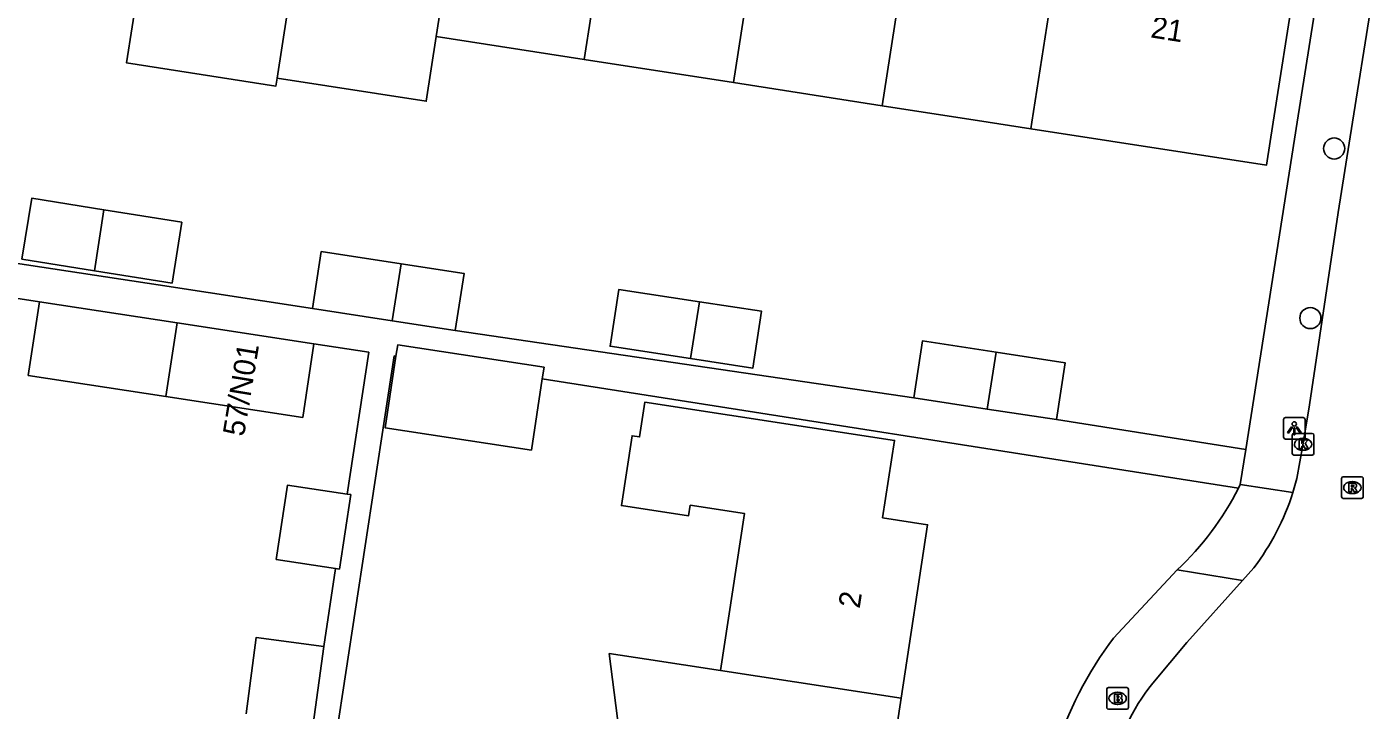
# Model space of a CAD drawing. Extents: x 161486 to 162249, y 379484 to 380829.
# Drawn here: x 162025.3 to 162087.4, y 380472.8 to 380504.4 of the extents above; entities that cross this region are included whole.
import ezdxf

# ---------------------------------------------------------------- set-up
doc = ezdxf.new("R2010")
doc.units = 0
for name, color, linetype in [('IMGEO_Boom', 7, 'Continuous'), ('IMGEO_Brandkraan', 7, 'Continuous'), ('IMGEO_Kolk', 7, 'Continuous'), ('IMGEO_Lichtpunt', 7, 'Continuous'), ('IMGEO_Pand', 7, 'Continuous'), ('IMGEO_Pand_nummerreeks', 7, 'Continuous'), ('IMGEO_Rijbaan_lokaal_open', 7, 'Continuous'), ('IMGEO_Rioolput', 7, 'Continuous'), ('IMGEO_Voetpad_open', 7, 'Continuous')]:
    doc.layers.add(name, color=color, linetype=linetype)

msp = doc.modelspace()

# ---------------------------------------------------------------- linework, layer by layer
at = {"layer": 'IMGEO_Boom'}
for centre in [(162085.83, 380498.777), (162084.729, 380490.922)]:
    msp.add_circle(centre, 0.489, dxfattribs=at)
at = {"layer": 'IMGEO_Brandkraan'}
for p, q in [((162075.306, 380472.888), (162075.306, 380473.74)), ((162075.381, 380473.814), (162076.233, 380473.814)), ((162075.794, 380473.594), (162075.819, 380473.594)), ((162076.307, 380473.74), (162076.307, 380472.888)), ((162076.233, 380472.814), (162075.381, 380472.814)), ((162075.817, 380473.034), (162075.792, 380473.034))]:
    msp.add_line(p, q, dxfattribs=at)
for points in [[(162075.306, 380472.888), (162075.306, 380473.74)], [(162075.381, 380473.814), (162076.233, 380473.814)], [(162075.654, 380473.514), (162075.654, 380473.114), (162075.867, 380473.114)], [(162075.885, 380473.514), (162075.654, 380473.514)], [(162075.833, 380473.433), (162075.779, 380473.433), (162075.779, 380473.357)], [(162075.779, 380473.357), (162075.832, 380473.357)], [(162075.841, 380473.281), (162075.779, 380473.281), (162075.779, 380473.2)], [(162075.779, 380473.2), (162075.841, 380473.2)], [(162076.307, 380473.74), (162076.307, 380472.888)], [(162076.233, 380472.814), (162075.381, 380472.814)]]:
    msp.add_lwpolyline(points, dxfattribs=at)
for centre, radius, start, end in [((162075.383, 380473.738), 0.0765, 91.55205, 178.44795), ((162075.383, 380473.738), 0.0765, 91.55205, 178.44795), ((162075.834, 380473.395), 0.0379, 267.82845, 90.93552), ((162075.842, 380473.24), 0.0404, 269.87594, 90.50774), ((162075.889, 380473.369), 0.145, 59.4692, 91.53667), ((162075.914, 380473.416), 0.0922, 285.51372, 58.15012), ((162075.919, 380473.224), 0.105, 301.31148, 78.98903), ((162076.231, 380473.738), 0.0765, 1.55205, 88.44795), ((162076.231, 380473.738), 0.0765, 1.55205, 88.44795), ((162075.383, 380472.89), 0.0765, 181.55205, 268.44795), ((162075.383, 380472.89), 0.0765, 181.55205, 268.44795), ((162075.873, 380473.365), 0.251, 268.66757, 293.53466), ((162076.231, 380472.89), 0.0765, 271.55205, 358.44795), ((162076.231, 380472.89), 0.0765, 271.55205, 358.44795)]:
    msp.add_arc(centre, radius, start, end, dxfattribs=at)
for centre, major_axis, ratio, start_param, end_param in [((162075.793, 380473.314), (-0.387, 0.002), 0.722429, 4.712389, 7.853982), ((162075.818, 380473.314), (-0.39, 0.002), 0.717154, 1.570796, 4.712389)]:
    msp.add_ellipse(centre, major_axis=major_axis, ratio=ratio, start_param=start_param, end_param=end_param, dxfattribs=at)
at = {"layer": 'IMGEO_Kolk'}
for p, q in [((162083.889, 380484.654), (162083.889, 380485.506)), ((162083.964, 380485.58), (162084.816, 380485.58)), ((162084.377, 380485.36), (162084.402, 380485.36)), ((162084.89, 380485.506), (162084.89, 380484.654)), ((162084.816, 380484.58), (162083.964, 380484.58)), ((162084.4, 380484.8), (162084.375, 380484.8))]:
    msp.add_line(p, q, dxfattribs=at)
for points in [[(162083.889, 380484.654), (162083.889, 380485.506)], [(162083.964, 380485.58), (162084.816, 380485.58)], [(162084.21, 380485.28), (162084.333, 380485.28), (162084.333, 380485.129), (162084.463, 380485.28), (162084.627, 380485.28), (162084.481, 380485.129), (162084.634, 380484.88), (162084.482, 380484.88), (162084.397, 380485.044), (162084.333, 380484.977), (162084.333, 380484.88), (162084.21, 380484.88), (162084.21, 380485.28)], [(162084.89, 380485.506), (162084.89, 380484.654)], [(162084.816, 380484.58), (162083.964, 380484.58)]]:
    msp.add_lwpolyline(points, dxfattribs=at)
for centre, start, end in [((162083.966, 380485.504), 91.55205, 178.44795), ((162083.966, 380485.504), 91.55205, 178.44795), ((162084.814, 380485.504), 1.55205, 88.44795), ((162084.814, 380485.504), 1.55205, 88.44795), ((162083.966, 380484.656), 181.55205, 268.44795), ((162083.966, 380484.656), 181.55205, 268.44795), ((162084.814, 380484.656), 271.55205, 358.44795), ((162084.814, 380484.656), 271.55205, 358.44795)]:
    msp.add_arc(centre, 0.0765, start, end, dxfattribs=at)
for centre, major_axis, ratio, start_param, end_param in [((162084.376, 380485.08), (-0.387, 0.002), 0.722429, 4.712389, 7.853982), ((162084.401, 380485.08), (-0.39, 0.002), 0.717154, 1.570796, 4.712389)]:
    msp.add_ellipse(centre, major_axis=major_axis, ratio=ratio, start_param=start_param, end_param=end_param, dxfattribs=at)
at = {"layer": 'IMGEO_Lichtpunt'}
for p, q in [((162084.388, 380486.319), (162083.58, 380486.319)), ((162084.388, 380486.319), (162083.58, 380486.319)), ((162083.486, 380486.224), (162083.486, 380485.417)), ((162083.486, 380486.224), (162083.486, 380485.417)), ((162084.482, 380485.417), (162084.482, 380486.224)), ((162084.482, 380485.417), (162084.482, 380486.224)), ((162083.58, 380485.323), (162084.388, 380485.323)), ((162083.58, 380485.323), (162084.388, 380485.323))]:
    msp.add_line(p, q, dxfattribs=at)
for points in [[(162083.86, 380485.888), (162083.899, 380485.86), (162083.711, 380485.598), (162083.673, 380485.625), (162083.86, 380485.888)], [(162083.962, 380485.84), (162084.009, 380485.84), (162084.009, 380485.518), (162083.962, 380485.518), (162083.962, 380485.84)], [(162084.072, 380485.86), (162084.11, 380485.887), (162084.297, 380485.625), (162084.258, 380485.597), (162084.072, 380485.86)]]:
    msp.add_lwpolyline(points, dxfattribs=at)
msp.add_circle((162083.985, 380486.022), 0.0994, dxfattribs=at)
for centre, start, end in [((162083.58, 380486.224), 90, 180), ((162083.58, 380486.224), 90, 180), ((162084.388, 380486.224), 0, 90), ((162084.388, 380486.224), 0, 90), ((162083.58, 380485.417), 180, 270), ((162083.58, 380485.417), 180, 270), ((162084.388, 380485.417), 270, 0), ((162084.388, 380485.417), 270, 360)]:
    msp.add_arc(centre, 0.0946, start, end, dxfattribs=at)
at = {"layer": 'IMGEO_Pand'}
for points in [[(162036.899, 380502.036), (162037.362, 380505.024), (162038.657, 380513.366)], [(162044.268, 380503.955), (162045.558, 380512.273)], [(162051.117, 380502.894), (162052.404, 380511.188)], [(162059.303, 380510.096), (162058.02, 380501.825)], [(162064.909, 380500.759), (162066.188, 380509.005)], [(162073.063, 380507.916), (162083.973, 380506.188), (162083.014, 380500), (162082.705, 380498.007), (162071.788, 380499.694)], [(162071.788, 380499.694), (162071.835, 380500), (162073.063, 380507.916)], [(162036.899, 380502.036), (162036.841, 380501.665), (162029.931, 380502.737), (162030.452, 380506.094)], [(162044.268, 380503.955), (162043.804, 380500.964), (162036.899, 380502.036)], [(162051.117, 380502.894), (162044.268, 380503.955)], [(162058.02, 380501.825), (162051.117, 380502.894)], [(162064.909, 380500.759), (162058.02, 380501.825)], [(162071.788, 380499.694), (162069.809, 380500), (162064.909, 380500.759)], [(162028.438, 380493.118), (162025.087, 380493.653), (162025.537, 380496.469), (162028.876, 380495.936)], [(162028.876, 380495.936), (162032.485, 380495.36), (162032.035, 380492.543), (162028.438, 380493.118)], [(162028.438, 380493.118), (162028.876, 380495.936)], [(162038.541, 380491.365), (162038.944, 380493.999), (162042.635, 380493.434)], [(162042.228, 380490.8), (162042.635, 380493.434)], [(162042.635, 380493.434), (162045.55, 380492.988), (162045.147, 380490.354)], [(162056.038, 380489.047), (162052.314, 380489.617), (162052.717, 380492.251), (162056.446, 380491.681)], [(162031.754, 380487.291), (162025.378, 380488.266), (162025.899, 380491.676)], [(162025.899, 380491.676), (162032.275, 380490.701)], [(162042.228, 380490.8), (162038.541, 380491.365)], [(162056.446, 380491.681), (162059.323, 380491.24), (162058.92, 380488.606), (162056.038, 380489.047)], [(162056.038, 380489.047), (162056.446, 380491.681)], [(162032.275, 380490.701), (162031.754, 380487.291)], [(162032.275, 380490.701), (162038.601, 380489.733)], [(162045.147, 380490.354), (162042.228, 380490.8)], [(162038.601, 380489.733), (162038.081, 380486.323), (162031.754, 380487.291)], [(162049.175, 380488.117), (162049.256, 380488.646), (162042.482, 380489.683), (162042.401, 380489.155)], [(162066.367, 380487.23), (162066.77, 380489.864), (162070.182, 380489.342)], [(162070.182, 380489.342), (162069.774, 380486.709)], [(162070.182, 380489.342), (162073.376, 380488.853), (162072.973, 380486.219)], [(162042.401, 380489.155), (162041.895, 380485.847), (162048.669, 380484.81), (162049.175, 380488.117)], [(162065.78, 380473.32), (162067.01, 380481.356), (162064.929, 380481.674), (162065.478, 380485.26), (162053.926, 380487.03), (162053.679, 380485.418), (162053.329, 380485.472), (162052.834, 380482.244), (162055.949, 380481.767), (162056.023, 380482.254), (162058.535, 380481.869), (162057.421, 380474.6)], [(162069.774, 380486.709), (162066.367, 380487.23)], [(162072.973, 380486.219), (162069.774, 380486.709)], [(162040.134, 380482.773), (162037.385, 380483.193), (162036.857, 380479.745), (162039.605, 380479.324)], [(162039.605, 380479.324), (162039.782, 380479.297), (162040.31, 380482.746), (162040.134, 380482.773)], [(162035.461, 380472.596), (162035.933, 380476.135), (162039.053, 380475.719)], [(162039.053, 380475.719), (162038.574, 380472.119)], [(162057.421, 380474.6), (162053.993, 380475.125), (162052.273, 380475.388), (162052.804, 380471.178), (162055.87, 380470.71), (162055.254, 380466.675), (162058.941, 380466.112), (162058.624, 380464.037), (162059.118, 380463.961), (162064.06, 380463.205), (162064.377, 380465.279), (162064.545, 380465.254), (162065.78, 380473.32)], [(162057.421, 380474.6), (162065.78, 380473.32)]]:
    msp.add_lwpolyline(points, dxfattribs=at)
at = {"layer": 'IMGEO_Rijbaan_lokaal_open'}
for points in [[(162083.917, 380482.84), (162084.104, 380483.496), (162084.383, 380485.034), (162084.683, 380486.901), (162086.012, 380495.812), (162086.678, 380500), (162087.493, 380505.123), (162088.551, 380511.284), (162088.645, 380511.945)], [(162082.112, 380479.358), (162081.583, 380478.771)], [(162081.583, 380478.771), (162079.004, 380475.906), (162077.434, 380474.016)]]:
    msp.add_lwpolyline(points, dxfattribs=at)
for centre, radius, start, end in [((162072.884, 380486.351), 11.578, 322.84754, 342.3498), ((162085.283, 380467.737), 10.051, 141.33868, 167.70024)]:
    msp.add_arc(centre, radius, start, end, dxfattribs=at)
at = {"layer": 'IMGEO_Rioolput'}
for p, q in [((162086.171, 380482.647), (162086.171, 380483.499)), ((162086.246, 380483.573), (162087.098, 380483.573)), ((162086.659, 380483.353), (162086.684, 380483.353)), ((162087.172, 380483.499), (162087.172, 380482.647)), ((162087.098, 380482.573), (162086.246, 380482.573)), ((162086.682, 380482.793), (162086.657, 380482.793))]:
    msp.add_line(p, q, dxfattribs=at)
for points in [[(162086.171, 380482.647), (162086.171, 380483.499)], [(162086.246, 380483.573), (162087.098, 380483.573)], [(162086.76, 380483.271), (162086.508, 380483.273), (162086.508, 380482.873)], [(162086.686, 380483.192), (162086.632, 380483.192), (162086.632, 380483.111)], [(162087.172, 380483.499), (162087.172, 380482.647)], [(162087.098, 380482.573), (162086.246, 380482.573)], [(162086.508, 380482.873), (162086.632, 380482.873), (162086.632, 380483.035), (162086.643, 380483.035)], [(162086.632, 380483.111), (162086.684, 380483.111)], [(162086.69, 380483.006), (162086.761, 380482.873), (162086.901, 380482.873), (162086.836, 380482.999)]]:
    msp.add_lwpolyline(points, dxfattribs=at)
for centre, radius, start, end in [((162086.248, 380483.497), 0.0765, 91.55205, 178.44795), ((162086.248, 380483.497), 0.0765, 91.55205, 178.44795), ((162086.692, 380483.096), 0.0964, 77.00612, 93.18647), ((162086.706, 380483.153), 0.0378, 276.66336, 79.67722), ((162086.759, 380483.161), 0.109, 350.36119, 89.41601), ((162086.757, 380483.161), 0.112, 277.58423, 350.98172), ((162087.096, 380483.497), 0.0765, 1.55205, 88.44795), ((162087.096, 380483.497), 0.0765, 1.55205, 88.44795), ((162086.248, 380482.649), 0.0765, 181.55205, 268.44795), ((162086.248, 380482.649), 0.0765, 181.55205, 268.44795), ((162086.642, 380482.982), 0.0533, 26.02933, 88.69889), ((162086.668, 380483.3), 0.19, 274.7715, 282.96867), ((162086.741, 380482.946), 0.108, 29.51342, 73.79051), ((162087.096, 380482.649), 0.0765, 271.55205, 358.44795), ((162087.096, 380482.649), 0.0765, 271.55205, 358.44795)]:
    msp.add_arc(centre, radius, start, end, dxfattribs=at)
for centre, major_axis, ratio, start_param, end_param in [((162086.658, 380483.073), (-0.387, 0.002), 0.722429, 4.712389, 7.853982), ((162086.683, 380483.073), (-0.39, 0.002), 0.717154, 1.570796, 4.712389)]:
    msp.add_ellipse(centre, major_axis=major_axis, ratio=ratio, start_param=start_param, end_param=end_param, dxfattribs=at)
at = {"layer": 'IMGEO_Voetpad_open'}
for points in [[(162081.739, 380484.84), (162084.124, 380500), (162085.825, 380510.811)], [(162009.511, 380495.807), (162024.782, 380493.47), (162031.388, 380492.459), (162038.541, 380491.365)], [(162009.269, 380494.234), (162025.899, 380491.676)], [(162045.147, 380490.354), (162066.367, 380487.23)], [(162038.601, 380489.733), (162041.141, 380489.344), (162040.134, 380482.773)], [(162039.182, 380468.642), (162042.32, 380489.168), (162042.401, 380489.155)], [(162049.175, 380488.117), (162081.4, 380483.045)], [(162072.973, 380486.219), (162081.739, 380484.84)], [(162081.739, 380484.84), (162081.483, 380483.21)], [(162081.4, 380483.045), (162081.483, 380483.21)], [(162081.483, 380483.21), (162083.917, 380482.84)], [(162039.605, 380479.324), (162039.053, 380475.719)], [(162075.622, 380476.102), (162078.568, 380479.267)], [(162078.568, 380479.267), (162081.583, 380478.771)]]:
    msp.add_lwpolyline(points, dxfattribs=at)
for centre, radius, start, end in [((162069.092, 380489.321), 13.816, 313.30569, 332.98364), ((162088.934, 380465.934), 16.751, 142.62521, 163.17257)]:
    msp.add_arc(centre, radius, start, end, dxfattribs=at)

# ---------------------------------------------------------------- texts
at = {"layer": 'IMGEO_Pand_nummerreeks'}
for s, rotation, p in [('21', 350.99934, (162077.3, 380503.925)), ('57/N01', 80.59266, (162035.361, 380485.409)), ('2', 81.29698, (162063.862, 380477.446))]:
    msp.add_text(s, height=1, rotation=rotation, dxfattribs=at).set_placement(p)

doc.saveas('drawing.dxf')
